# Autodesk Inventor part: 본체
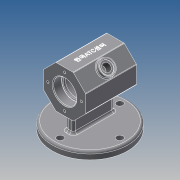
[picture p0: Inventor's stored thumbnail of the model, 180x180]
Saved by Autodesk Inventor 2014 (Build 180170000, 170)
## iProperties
Created: 2021-02
Part Number: 본체
Material: 일반
Document SubType Name: Modeling
Designer: kbl
Density: 1 g/cm^3
Appearance: 기본값
Mass: 206.19 g
Surface Area: 509.942 cm^2
Volume: 206.19 cm^3
Author: kbl
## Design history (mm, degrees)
sketch "스케치1"
  geometry: L1 (12.012, 29)-(29, 12.012); L2 (29, 12.012)-(29, -12.012); L3 (29, -12.012)-(12.012, -29); L4 (12.012, -29)-(-12.012, -29); L5 (-12.012, -29)-(-29, -12.012); L6 (-29, -12.012)-(-29, 12.012); L7 (-29, 12.012)-(-12.012, 29); L8 (-12.012, 29)-(12.012, 29); C1 r 29 at (0, 0); 2 further points
  constraints: 16 end point, 2 coincident, 1 centre point, 1 horizontal, 1 tangent, 17 other
  dimensions: "d0" = 58 diameter of C1
extrude "돌출1" new body sketch "스케치1" stored distance "d1" = 70; taper "d2" = 0 deg
sketch "스케치2"
  geometry: L1 (29, 35)-(12.012, 35) reference; L2 (12.012, 35)-(-12.012, 35) reference; L3 (-12.012, 35)-(-29, 35) reference; L4 (12.012, -35)-(29, -35) reference; L5 (-12.012, -35)-(12.012, -35) reference; L6 (-29, -35)-(-12.012, -35) reference; L7 (0, 35)-(0, -35); L8 (16, 35)-(16, 23.3); L9 (15.7, 23)-(14, 23); L10 (14, 23)-(14, 20); L11 (14, 20)-(19, 20); L12 (22, 17)-(22, -17); L13 (19, -20)-(14, -20); L14 (14, -20)-(14, -23); L15 (14, -23)-(15.7, -23); L16 (16, -23.3)-(16, -35); A1 r 3 centre (19, -17) between (19, -20) and (22, -17); A2 r 3 centre (19, 17) between (22, 17) and (19, 20); A3 r 0.3 centre (15.7, -23.3) between (16, -23.3) and (15.7, -23); A4 r 0.3 centre (15.7, 23.3) between (15.7, 23) and (16, 23.3); 5 further points
  constraints: 20 end point, 10 point on line, 8 point on circle, 8 tangent, 7 parallel, 4 centre point, 2 collinear, 2 equal radius, 2 midpoint, 1 perpendicular
  dimensions: "d3" = 28 diameter of L10 L7; "d4" = 28 diameter of L14 L7; "d5" = 32 diameter of L16 L7; "d6" = 32 diameter of L8 L7; "d7" = 44 diameter of L12 L7; "d9" = 12 distance of point (16, -23) L16.end; "d11" = 12 distance of L8.start point (16, 23); "d13" = 40 distance of point (22, 20) point (22, -20); "d15" = 3 radius of A1; "d40" = 0.3 radius of A3
revolve "회전1" sketch "스케치2" stored, may be unused: angle "d14" = 90 deg
chamfer "모따기1" distance "d16" = 1; stored, may be unused: second distance "d17" = 2, angle "d18" = 45 deg
sketch "스케치3"
  geometry: C1 r 17 at (0, 0) reference; 1 further point
  constraints: 1 vertical alignment
  dimensions: "d19" = 23 distance of C1.centre point (0, 23)
hole "구멍1" sketch "스케치3" at (0, 23) diameter "d20" = 3.242; stored, may be unused: countersink angle "d24" = 90 deg, drill point angle "d26" = 118 deg; dims "d21" = 8, "d22" = 4, "d23" = 2, "d25" = 10
node "작업 평면1"
sketch "스케치4"
  geometry: C1 r 52 at (0, 0); C2 r 4.5 at (0, 41); C3 r 4.5 at (0, -41); C4 r 4.5 at (41, 0); C5 r 4.5 at (-41, 0); A1 r 41 centre (0, 0) between (0, 41) and (0, -41); 1 further point
  constraints: 6 centre point, 4 point on circle, 3 equal radius, 2 coincident, 2 horizontal alignment, 2 vertical alignment
  dimensions: "d31" = 104 diameter of C1; "d32" = 82 diameter of A1; "d33" = 9 diameter of C4
extrude "돌출2" join sketch "스케치4" distance "d34" = 10; taper "d35" = 0 deg
sketch "스케치5"
  geometry: L1 (-5, -28)-(5, -28); L2 (5, -28)-(5, 28); L3 (5, 28)-(-5, 28); L4 (-5, 28)-(-5, -28); L5 (-5, -28)-(5, 28); L6 (5, -28)-(-5, 28); C1 r 52 at (0, 0) reference
  constraints: 12 end point, 2 midpoint, 2 parallel, 1 horizontal, 1 perpendicular
  dimensions: "d36" = 10 distance of L2.end L3.end; "d37" = 56 distance of L1.end L2.end
extrude "돌출3" join sketch "스케치5" stored distance "d38" = 10; taper "d39" = 0 deg
sketch "스케치6"
  geometry: C1 r 10 at (-12.012, 35); 1 further point
  constraints: 1 centre point, 1 coincident
  dimensions: "d41" = 20 diameter of C1
extrude "돌출4" join sketch "스케치6" distance "d42" = 5; taper "d43" = 0 deg
hole "구멍2" diameter "d46" = 16; stored, may be unused: countersink angle "d50" = 90 deg, drill point angle "d52" = 0 deg; dims "d47" = 8, "d48" = 4, "d49" = 2, "d51" = 2, "d55" = 10, "d56" = 10
hole "구멍3" diameter "d57" = 10.917; stored, may be unused: countersink angle "d61" = 90 deg, drill point angle "d63" = 118 deg; dims "d58" = 8, "d59" = 4, "d60" = 2, "d62" = 2, "d66" = 10, "d67" = 10
chamfer "모따기2" distance "d64" = 1; stored, may be unused: second distance "d65" = 2, angle "d68" = 45 deg
sketch "스케치7"
  geometry: L1 (24.024, 0)-(0, 0) reference; L2 (-16.988, 0)-(-16.988, 70) reference; 2 further points
  constraints: 1 other
  dimensions: "d69" = 35 distance from line of point (12.012, 35) L1; "d70" = 29 distance from line of point (12.012, 35) L2
feature "엠보싱1" sketch "스케치7" dims "d0" = 58, "d71" = 0.5, "d72" = 0
fillet "모깎기1" dims "d73" = 1, "d74" = 3
fillet "모깎기2" dims "d75" = 3
node "솔리드1"
pattern_circular "원형 패턴1" dims angle "d28" = 360 deg
mirror "대칭1"
other parameters: "d30" = -62
